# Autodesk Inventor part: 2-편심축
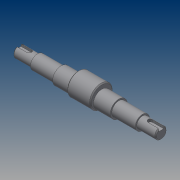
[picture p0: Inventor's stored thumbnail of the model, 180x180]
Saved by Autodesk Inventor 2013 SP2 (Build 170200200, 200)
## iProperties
Created: 2014-12
Part Number: 2-편심축
Material: Generic
Document SubType Name: Modeling
Designer: CADB102
Density: 1 g/cm^3
Author: CADB102
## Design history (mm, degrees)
sketch "스케치1"
  geometry: L1 (-75.5, 0)-(-75.5, 6); L2 (-75.5, 6)-(-55.5, 6); L3 (-55.5, 6)-(-55.5, 7.5); L4 (-55.5, 7.5)-(-30.5, 7.5); L5 (-30.5, 7.5)-(-30.5, 9); L6 (-30.5, 9)-(30.5, 9); L7 (30.5, 9)-(30.5, 7.5); L8 (30.5, 7.5)-(55.5, 7.5); L9 (55.5, 7.5)-(55.5, 6); L10 (55.5, 6)-(75.5, 6); L11 (75.5, 6)-(75.5, 0); L12 (75.5, 0)-(-75.5, 0); L13 (-12.5, 14)-(12.5, 14); L14 (12.5, 14)-(12.5, 2); L15 (12.5, 2)-(-12.5, 2); L16 (-12.5, 2)-(-12.5, 14); L17 (-80.948, 11.564)-(-61.5, 11.564); L18 (-61.5, 11.564)-(-61.5, 3); L19 (-61.5, 3)-(-80.948, 3); L20 (-80.948, 3)-(-80.948, 11.564); L21 (61.5, 11.564)-(81.844, 11.564); L22 (81.844, 11.564)-(81.844, 3); L23 (81.844, 3)-(61.5, 3); L24 (61.5, 3)-(61.5, 11.564); 2 further points
  constraints: 48 end point, 15 parallel, 4 perpendicular, 3 horizontal, 2 coincident, 1 collinear, 1 midpoint, 1 vertical
  dimensions: "d0" = 12 diameter of L2 L12; "d2" = 15 diameter of L4 L12; "d3" = 18 diameter of L6 L12; "d4" = 15 diameter of L8 L12; "d5" = 12 diameter of L10 L12; "d6" = 151 distance of L11.end L1.start; "d7" = 20 distance of L9.end L10.end; "d8" = 25 distance of L7.end L8.end; "d9" = 20 distance of L1.end L2.end; "d10" = 25 distance of L3.end L4.end; "d12" = 2 distance from line of L11.end L15; "d13" = 24 diameter of L13 L15; "d14" = 18 distance between parallel lines of L16 L5; "d15" = 18 distance between parallel lines of L7 L14; "d16" = 3 distance between parallel lines of L2 L19; "d17" = 14 distance between parallel lines of L1 L18; "d18" = 3 distance between parallel lines of L10 L23; "d19" = 14 distance between parallel lines of L11 L24
revolve "회전1" stored, may be unused: angle "d20" = 90 deg
revolve "회전2" stored, may be unused: angle "d21" = 90 deg
extrude "돌출1" cut sketch "스케치1" stored distance "d22" = 5; taper "d23" = 0 deg
fillet "모깎기1" dims "d24" = 2.5
chamfer "모따기1" distance "d25" = 1; stored, may be unused: second distance "d26" = 2, angle "d27" = 45 deg
node "솔리드1"
